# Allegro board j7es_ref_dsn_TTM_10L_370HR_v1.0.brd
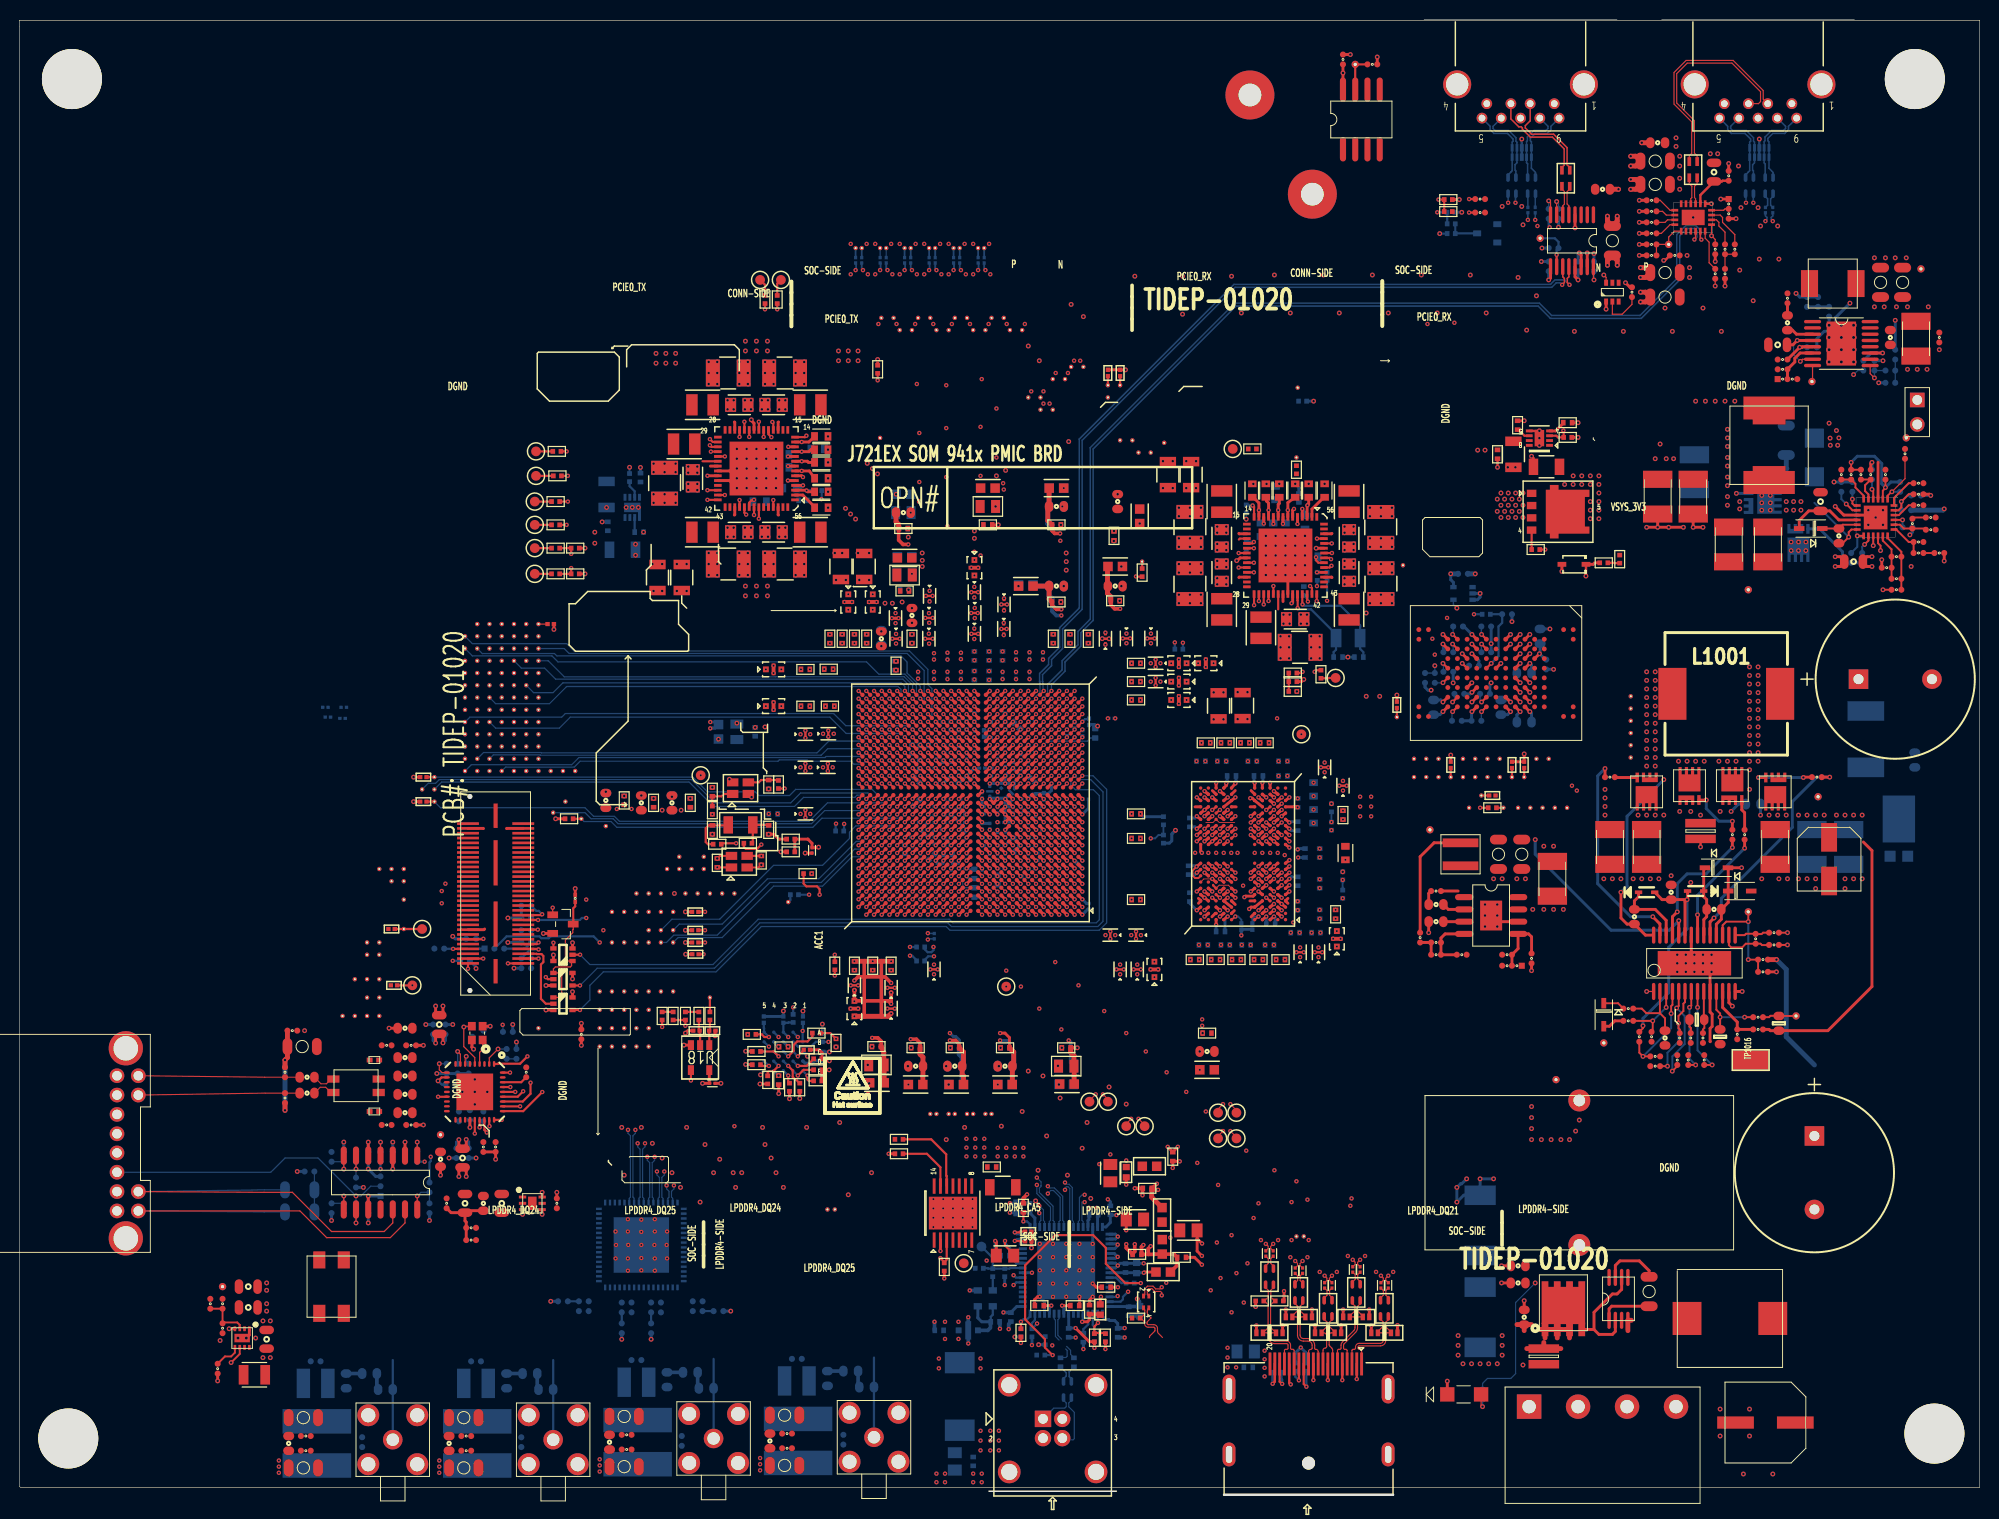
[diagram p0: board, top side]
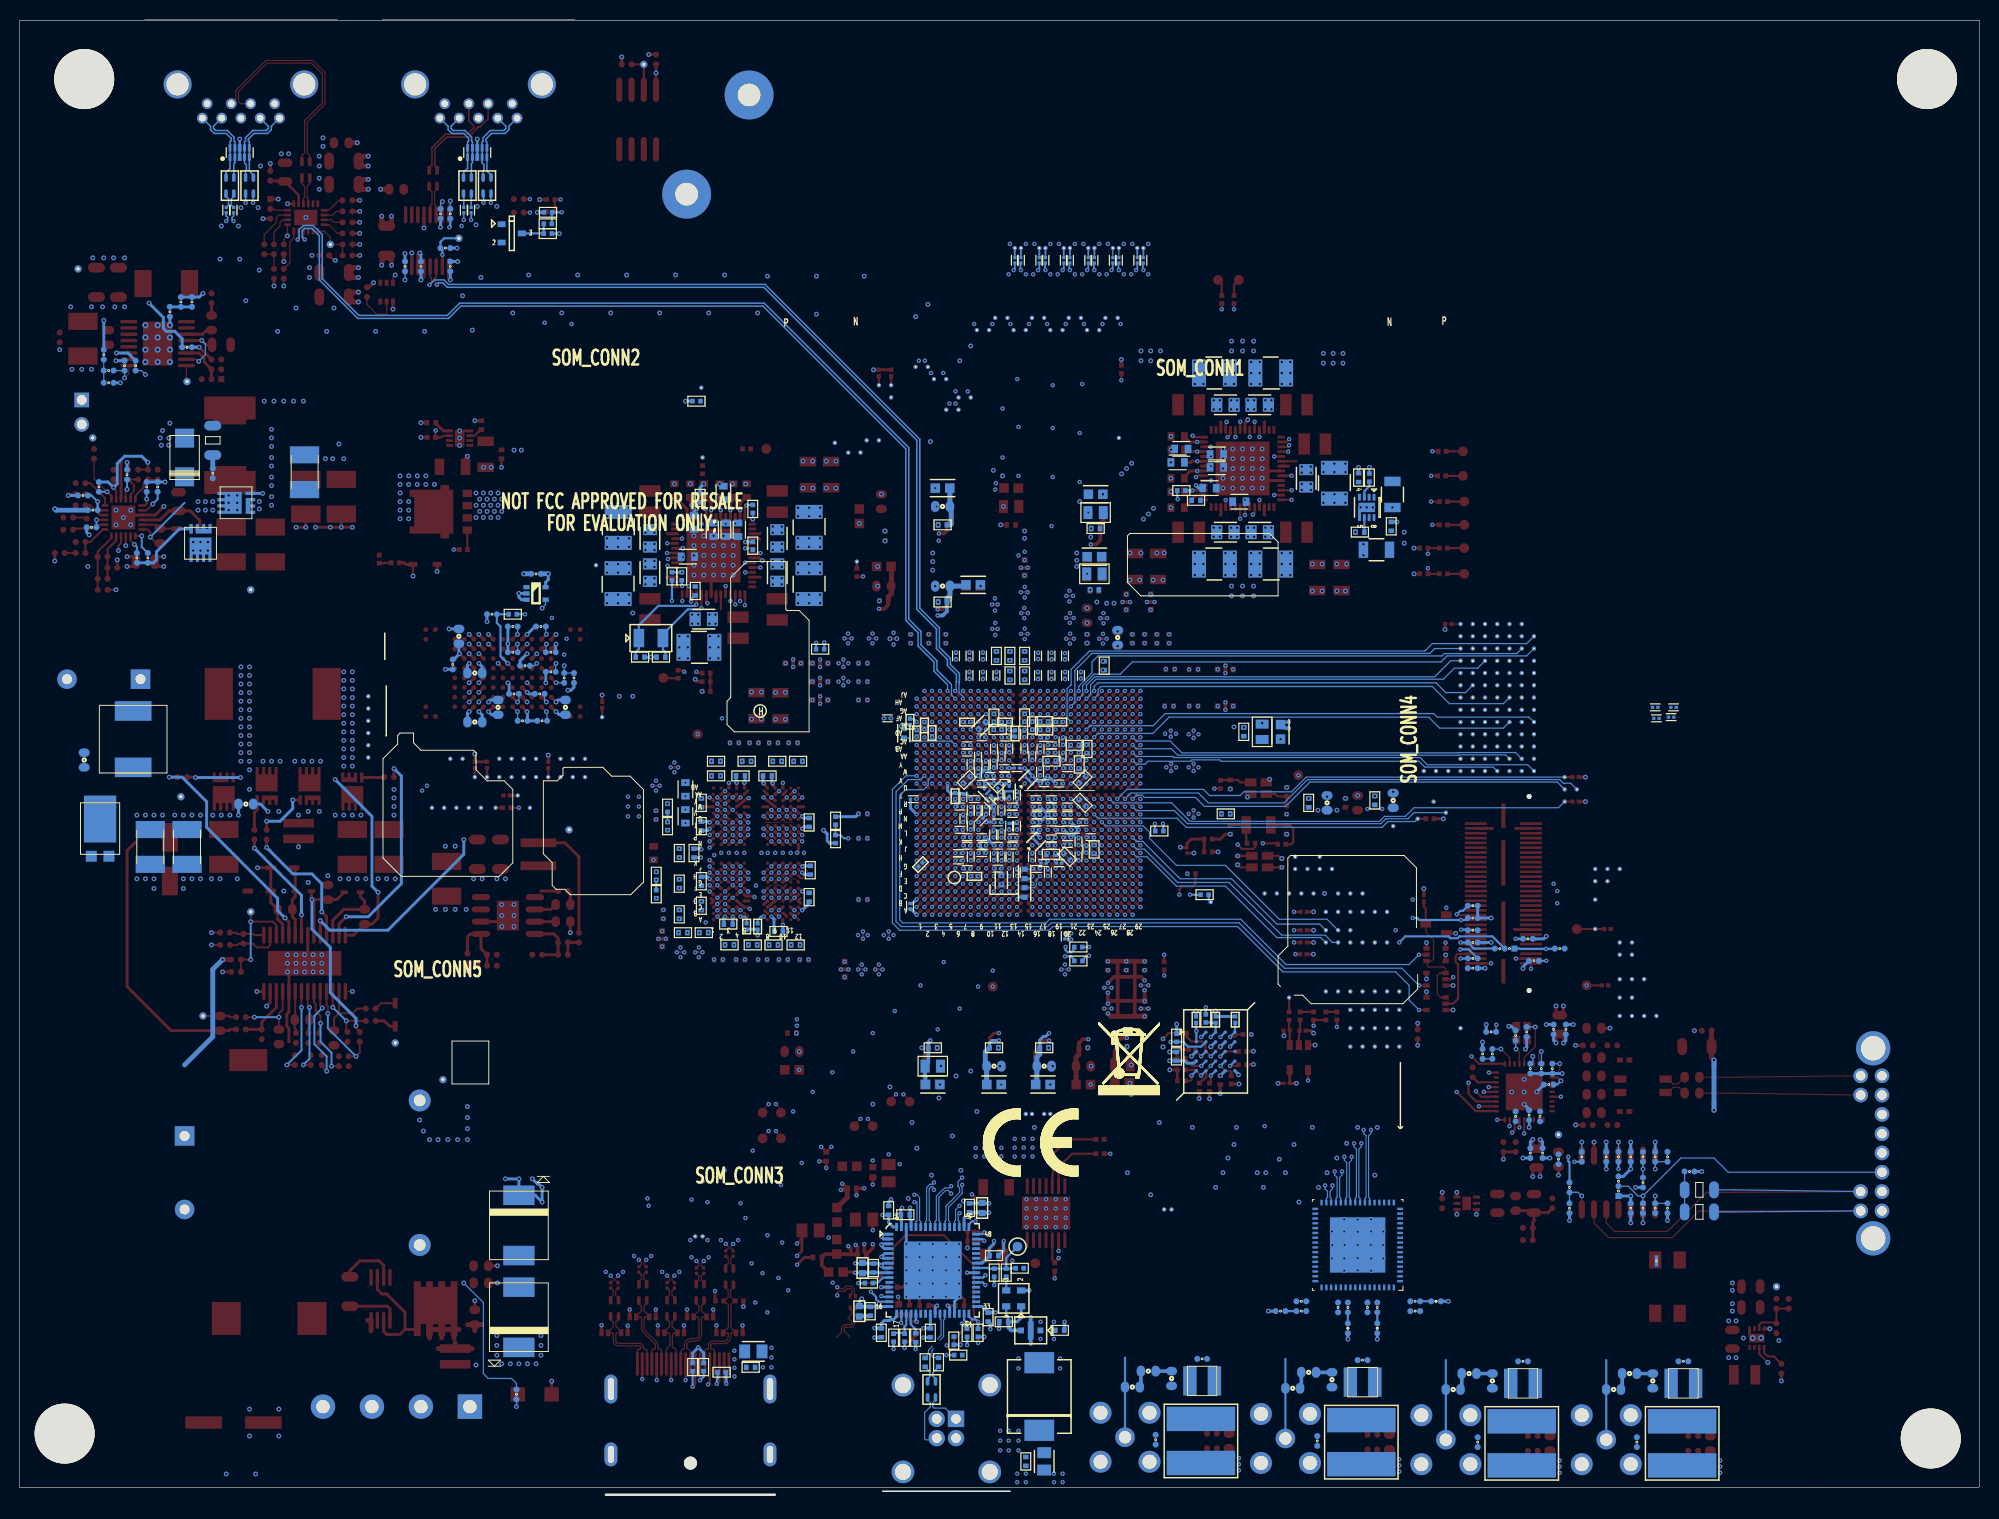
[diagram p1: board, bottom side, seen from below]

Outline 203.33 x 153 mm; copper layers: TOP, L2-SIGNAL, L3-GND, L4-SIGNAL, L5-PWR/GND, L6-PWR/GND, L7-SIGNAL, L8-GND, L9-SIGNAL, BOTTOM. Coordinates in mm from the lower left corner of the outline.
Outline path: 0,152.9 0,0.88 0.13,0.75 203.33,0.75 203.33,152.9 0,152.9

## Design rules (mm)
net group C_PCIE0_TX0: nets C_PCIE0_TX0_N C_PCIE0_TX0_P
net group C_PCIE1_TX0: nets C_PCIE1_TX0_N C_PCIE1_TX0_P
net group C_PCIE1_TX1: nets C_PCIE1_TX1_N C_PCIE1_TX1_P
net group C_PCIE2_TX0: nets C_PCIE2_TX0_N C_PCIE2_TX0_P
net group C_SGMII2_TX0: nets C_SGMII2_TX0_N C_SGMII2_TX0_P
net group C_UB981_DOUT0: nets C_UB981_DOUT0_N C_UB981_DOUT0_P
net group C_USB_SS_TX1: nets C_USB_SS_TX1_N C_USB_SS_TX1_P
net group C_USB_SS_TX2: nets C_USB_SS_TX2_N C_USB_SS_TX2_P
net group CAM_0: nets CAM_0_N CAM_0_P
net group CAM_1: nets CAM_1_N CAM_1_P
net group CAM_2: nets CAM_2_N CAM_2_P
net group CAM_3: nets CAM_3_N CAM_3_P
net group CLKGEN_USB_REFCLK: nets CLKGEN_USB_REFCLK_N CLKGEN_USB_REFCLK_P
net group CON_DP0_AUX: nets CON_DP0_AUX_N CON_DP0_AUX_P
net group CON_DP0_TX0: nets CON_DP0_TX0_N CON_DP0_TX0_P
net group CON_DP0_TX1: nets CON_DP0_TX1_N CON_DP0_TX1_P
net group CONN_USB1_D: nets CONN_USB1_DM CONN_USB1_DP
net group CSI0_RX0: nets CSI0_RX0_N CSI0_RX0_P
net group CSI0_RX1: nets CSI0_RX1_N CSI0_RX1_P
net group CSI0_RX2: nets CSI0_RX2_N CSI0_RX2_P
net group CSI0_RX3: nets CSI0_RX3_N CSI0_RX3_P
net group DP0_AUX: nets DP0_AUX_N DP0_AUX_P
net group MMC0: nets MMC0_CLK MMC0_DS
net group PCIE0_RX0: nets PCIE0_RX0_N PCIE0_RX0_P
net group PCIE0_TX0: nets PCIE0_TX0_N PCIE0_TX0_P
net group PCIE1_RX0: nets PCIE1_RX0_N PCIE1_RX0_P
net group PCIE1_RX1: nets PCIE1_RX1_N PCIE1_RX1_P
net group PCIE1_TX0: nets PCIE1_TX0_N PCIE1_TX0_P
net group PCIE1_TX1: nets PCIE1_TX1_N PCIE1_TX1_P
net group PCIE2_RX0: nets PCIE2_RX0_N PCIE2_RX0_P
net group PCIE2_RX1: nets PCIE2_RX1_N PCIE2_RX1_P
net group PCIE2_TX0: nets PCIE2_TX0_N PCIE2_TX0_P
net group PCIE2_TX1: nets PCIE2_TX1_N PCIE2_TX1_P
net group SGMII2_TX0: nets SGMII2_TX0_N SGMII2_TX0_P
net group SOC_SERDES0_REFCLK: nets SOC_SERDES0_REFCLK_N SOC_SERDES0_REFCLK_P
net group SOC_SERDES1_REFCLK: nets SOC_SERDES1_REFCLK_N SOC_SERDES1_REFCLK_P
net group SOC_SERDES2_REFCLK: nets SOC_SERDES2_REFCLK_N SOC_SERDES2_REFCLK_P
net group TRD: nets TRD_N TRD_P
net group TRD1: nets TRD1_N TRD1_P
net group UFS0_RX0: nets UFS0_RX0_N UFS0_RX0_P
net group UFS0_RX1: nets UFS0_RX1_N UFS0_RX1_P
net group UFS0_TX0: nets UFS0_TX0_N UFS0_TX0_P
net group UFS0_TX1: nets UFS0_TX1_N UFS0_TX1_P
net group USB1_D: nets USB1_DM USB1_DP
net group USB2_D: nets USB2_DM USB2_DP
net group USBC_SS_RX1: nets USBC_SS_RX1_N USBC_SS_RX1_P
net group USBC_SS_RX2: nets USBC_SS_RX2_N USBC_SS_RX2_P
net group USBC_SS_TX1: nets USBC_SS_TX1_N USBC_SS_TX1_P
net group USBC_SS_TX2: nets USBC_SS_TX2_N USBC_SS_TX2_P
net group 40-OHM_PH: nets LPDDR4_CA0 LPDDR4_CA1 LPDDR4_CA2 LPDDR4_CA3 LPDDR4_CA4 LPDDR4_CA5 LPDDR4_CKE0 LPDDR4_CKE1 LPDDR4_CSN0_0 LPDDR4_CSN0_1 LPDDR4_CSN1_0 LPDDR4_CSN1_1
net group MCU_OSPI0: nets MCU_OSPI0_CLK MCU_OSPI0_DQS OSPI_DQS_R
net group MCU_OSPI1: nets MCU_OSPI1_CLK MCU_OSPI1_CLK_R N24594267
net group MCU_RGMII1_T: nets MCU_RGMII1_TD0 MCU_RGMII1_TD1 MCU_RGMII1_TD2 MCU_RGMII1_TD3 MCU_RGMII1_TX_CTL MCU_RGMII1_TXC
net group MMC1: nets MMC1_CLK MMC1_CMD MMC1_DAT0 MMC1_DAT1 MMC1_DAT2 MMC1_DAT3
net group PRG0_RGMII1: nets MCASP0_AXR7/PRG0_RGMII1_TD0 MCASP0_AXR8/PRG0_RGMII1_TD1 MCASP0_AXR9/PRG0_RGMII1_TD2 MCASP0_AXR10/PRG0_RGMII1_TD3 MCASP0_AXR11/PRG0_RGMII1_TX_CTL MCASP0_AXR12/PRG0_RGMII1_TXC
net group PRG0_RGMII2_T: nets GPIO0_78/PRG0_RGMII2_TX_CTL GPIO0_79/PRG0_RGMII2_TXC MCASP1_AXR7/PRG0_RGMII2_TD0 MCASP1_AXR8/PRG0_RGMII2_TD1 PRG0_RGMII2_TD2 PRG0_RGMII2_TD3
net group PWR_PH: nets VCC_LM5141 VCC_LM5175 VDDA_LM5141 VDDI_MMC2 VOSNS
net group SOC_MCU_OSPI0: nets SOC_MCU_OSPI0_CLK_R
net group VOUT0_GROUP: nets VOUT0_DATA11/PRG1_RGMII2_TD0 VOUT0_DATA12/PRG1_RGMII2_TD1 VOUT0_DATA13/PRG1_RGMII2_TD2 VOUT0_DATA14/PRG1_RGMII2_TD3 VOUT0_DATA15/PRG1_RGMII2_TX_CTL VOUT0_DATA16/PRG1_RGMII1_TD0 VOUT0_DATA17/PRG1_RGMII1_TD1 VOUT0_DATA18/PRG1_RGMII1_TD2 VOUT0_DATA19/PRG1_RGMII1_TD3 VOUT0_DATA20/PRG1_RGMII1_TX_CTL VOUT0_DATA21/PRG1_RGMII1_TXC VOUT0_HSYNC/PRG1_RGMII2_TXC VOUT0_PCLK/SPI6_D1

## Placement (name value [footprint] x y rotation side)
C26  47uF  [CAP1206_2]  66.19 95.11 90 top
C27  47uF  [CAP1206_2]  68.71 95.11 90 top
C28  47uF  [CAP1206_2]  85.22 96.26 90 top
C29  47uF  [CAP1206_2]  87.63 96.26 90 top
C30  1uF  [CAP0402_0-75]  100.46 100.57 0 top
C31  22uF  [CAP0805_1-25]  100.46 102.48 0 top
C32  1uF  [EMIFIL_NFM15CC_0402_0-5]  94.41 93.21 270 top
C33  10uF  [EMIFIL_NFM18C_0603_0-7]  99.06 96.13 270 top
C34  1uF  [CAP0402_0-75]  91.69 100.19 0 top
C35  4.7uF  [C603-35X45]  91.69 101.84 0 top
C37  1uF  [EMIFIL_NFM15CC_0402_0-5]  99.1 91.43 270 top
C38  1uF  [EMIFIL_NFM15CC_0402_0-5]  99.06 93.59 270 top
C41  10uF  [EMIFIL_NFM18C_0603_0-7]  85.98 92.57 270 top
C42  10uF  [EMIFIL_NFM18C_0603_0-7]  88.52 92.57 270 top
C43  1uF  [CAP0402_0-75]  91.82 93.84 0 bottom
C44  22uF  [CAP0805_1-25]  91.82 95.49 0 bottom
C45  1uF  [CAP0402_0-75]  107.57 100.57 0 top
C46  4.7uF  [C603-35X45]  107.57 102.48 0 top
C47  1uF  [CAP0402_0-75]  107.57 92.57 0 top
C48  4.7uF  [C603-35X45]  107.57 94.22 0 top
C49  1uF  [CAP0402_0-75]  113.66 92.7 0 top
C50  4.7uF  [C603-35X45]  113.66 94.22 0 top
C53  1uF  [EMIFIL_NFM15CC_0402_0-5]  90.88 90.9 270 top
C54  1uF  [EMIFIL_NFM15CC_0402_0-5]  83.91 78.91 0 top
C55  47uF  [CAP1206_2]  119.13 105.78 90 top
C56  47uF  [CAP1206_2]  121.54 105.78 90 top
C57  1uF  [EMIFIL_NFM15CC_0402_0-5]  114.83 88.79 270 top
C58  1uF  [EMIFIL_NFM15CC_0402_0-5]  117.37 88.79 270 top
C59  10uF  [EMIFIL_NFM18C_0603_0-7]  78.23 81.78 0 top
C60  0.47uF  [CAP0402_0-75]  84.07 88.76 90 top
C61  0.47uF  [CAP0402_0-75]  85.34 88.76 90 top
C62  0.47uF  [CAP0402_0-75]  86.61 88.76 90 top
C63  0.47uF  [CAP0402_0-75]  87.88 88.76 90 top
C64  1uF  [EMIFIL_NFM15CC_0402_0-5]  99.06 89.27 270 top
C65  1uF  [EMIFIL_NFM15CC_0402_0-5]  94.35 90.92 270 top
C66  1uF  [EMIFIL_NFM15CC_0402_0-5]  94.34 88.76 270 top
C67  1uF  [EMIFIL_NFM15CC_0402_0-5]  90.93 88.76 270 top
C68  1uF  [EMIFIL_NFM15CC_0402_0-5]  102.87 72.84 45 bottom
C69  1uF  [EMIFIL_NFM15CC_0402_0-5]  100.66 72.94 270 bottom
C70  1uF  [EMIFIL_NFM15CC_0402_0-5]  112.65 88.76 90 top
C71  0.47uF  [CAP0402_0-75]  108.97 88.76 90 top
C72  0.47uF  [CAP0402_0-75]  110.87 88.76 90 top
C73  0.47uF  [CAP0402_0-75]  107.24 88.76 90 top
C78  10uF  [EMIFIL_NFM18C_0603_0-7]  120.27 86.22 180 top
C79  0.47uF  [CAP0402_0-75]  115.82 86.22 0 top
C80  10uF  [EMIFIL_NFM18C_0603_0-7]  78.23 85.59 0 top
C81  0.47uF  [CAP0402_0-75]  81.53 85.59 180 top
C82  0.47uF  [CAP0402_0-75]  115.82 84.32 0 top
C83  47uF  [CAP1206_2]  126.87 81.83 270 top
C84  10uF  [EMIFIL_NFM18C_0603_0-7]  120.27 84.32 180 top
C85  0.47uF  [CAP0402_0-75]  84.07 81.78 180 top
C86  0.1uF  [CAP0402_0-75]  160.59 111.17 0 top
C87  0.47uF  [CAP0402_0-75]  115.82 82.41 0 top
C88  22uF  [CAP1206_2]  158.39 106.59 180 top
C89  220pF  [CAP0402_0-75]  155.4 110.91 90 top
C90  0.47uF  [CAP0402_0-75]  81.53 81.78 180 top
C91  10uF  [EMIFIL_NFM18C_0603_0-7]  120.27 82.41 180 top
C92  47uF  [CAP1206_2]  124.38 81.8 270 top
C93  1uF  [EMIFIL_NFM15CC_0402_0-5]  117.86 84.32 180 top
C94  0.47uF  [CAP0402_0-75]  83.95 85.61 180 top
C95  10uF  [EMIFIL_NFM18C_0603_0-7]  123.06 86.22 180 top
C96  0.1uF  [CAP0402_0-75]  153.31 107.89 270 top
C97  22uF  [CAP1206_2]  154.97 107.89 270 top
C98  1uF  [EMIFIL_NFM15CC_0402_0-5]  97.87 67.73 135 bottom
C99  1uF  [EMIFIL_NFM15CC_0402_0-5]  81.53 78.86 0 top
C100  1uF  [EMIFIL_NFM15CC_0402_0-5]  117.86 86.22 180 top
C101  0.01uF  [CAP0402_0-75]  123.06 77.97 0 top
C102  0.1uF  [CAP0402_0-75]  129.16 77.97 0 top
C104  4.7uF  [C603-35X45]  60.83 72 90 top
C105  4.7uF  [C603-35X45]  92.58 91.18 90 top
C106  1uF  [EMIFIL_NFM15CC_0402_0-5]  98.68 74.16 135 bottom
C107  1uF  [EMIFIL_NFM15CC_0402_0-5]  81.53 75.43 0 top
C110  30pF  [CAP0402_0-75]  77.72 73.65 270 top
C111  1uF  [CAP0402_0-75]  62.74 72 90 top
C112  1uF  [CAP0402_0-75]  92.58 88.76 90 top
C114  30pF  [CAP0402_0-75]  71.88 72.89 90 top
C118  1uF  [EMIFIL_NFM15CC_0402_0-5]  83.86 75.43 0 top
C119  1uF  [EMIFIL_NFM15CC_0402_0-5]  81.53 70.6 0 top
C120  0.47uF  [CAP0402_0-75]  115.82 70.6 0 top
C121  22uF  [CAP0805_1-25]  88.9 44.57 180 top
C122  4.7uF  [C603-35X45]  67.69 71.74 90 top
C124  18pF  [CAP0402_0-75]  71.88 68.95 270 top
C125  18pF  [CAP0402_0-75]  77.72 68.95 270 top
C128  0.47uF  [CAP0402_0-75]  115.82 68.06 0 top
C130  1uF  [CAP0402_0-75]  88.9 46.47 180 top
C131  1uF  [CAP0402_0-75]  69.6 71.74 90 top
C132  0.1uF  [CAP0201_0-5]  82.22 66.82 270 top
C133  10uF  [CAP0603_1]  137.54 66.54 270 top
C135  12pF  [CAP0402_0-75]  76.96 65.78 270 top
C136  12pF  [CAP0402_0-75]  72.39 65.52 90 top
C141  0.47uF  [CAP0402_0-75]  115.82 61.71 0 top
C149  1uF  [EMIFIL_NFM15CC_0402_0-5]  115.82 58.03 180 top
C155  1uF  [CAP0402_0-75]  126.24 55.49 0 top
C156  0.01uF  [CAP0402_0-75]  130.81 55.49 0 top
C157  0.47uF  [CAP0402_0-75]  86.61 54.85 270 top
C158  0.47uF  [CAP0402_0-75]  88.52 54.85 270 top
C159  0.47uF  [CAP0402_0-75]  90.42 54.85 270 top
C160  1uF  [EMIFIL_NFM15CC_0402_0-5]  90.42 52.57 90 top
C161  1uF  [EMIFIL_NFM15CC_0402_0-5]  94.87 54.47 90 top
C162  0.47uF  [CAP0402_0-75]  125.09 77.97 0 top
C163  0.47uF  [CAP0402_0-75]  127.13 77.97 0 top
C164  0.47uF  [CAP0402_0-75]  124.08 55.49 0 top
C165  0.47uF  [CAP0402_0-75]  136.52 60.19 270 top
C166  1uF  [EMIFIL_NFM15CC_0402_0-5]  135.38 75.43 90 top
C167  1uF  [EMIFIL_NFM15CC_0402_0-5]  113.16 58.03 180 top
C168  1uF  [EMIFIL_NFM15CC_0402_0-5]  114.17 54.47 90 top
C169  0.47uF  [CAP0402_0-75]  137.29 70.47 270 top
C173  0.1uF  [CAP0201_0-5]  71.88 42.66 0 top
C177  0.47uF  [CAP0402_0-75]  128.52 55.49 0 top
C178  0.47uF  [CAP0402_0-75]  121.92 55.49 0 top
C179  1uF  [EMIFIL_NFM15CC_0402_0-5]  137.29 73.52 90 top
C180  1uF  [EMIFIL_NFM15CC_0402_0-5]  134.75 56.25 90 top
C181  1uF  [EMIFIL_NFM15CC_0402_0-5]  115.95 54.47 90 top
C182  10uF  [EMIFIL_NFM18C_0603_0-7]  117.73 54.47 90 top
C184  10uF  [EMIFIL_NFM18C_0603_0-7]  86.61 50.41 90 top
C185  4.7uF  [C603-35X45]  92.96 44.44 180 top
C186  1uF  [CAP0402_0-75]  92.96 46.34 180 top
C187  4.7uF  [C603-35X45]  97.03 44.44 180 top
C188  1uF  [CAP0402_0-75]  97.03 46.34 180 top
C189  22uF  [CAP0805_1-25]  108.58 44.44 180 top
C190  1uF  [CAP0402_0-75]  108.58 46.34 180 top
C192  10uF  [EMIFIL_NFM18C_0603_0-7]  136.65 57.65 90 top
C193  1uF  [EMIFIL_NFM15CC_0402_0-5]  132.84 56.25 90 top
C197  1uF  [EMIFIL_NFM15CC_0402_0-5]  90.42 50.41 90 top
C198  1uF  [EMIFIL_NFM15CC_0402_0-5]  86.61 52.82 90 top
C199  4.7uF  [C603-35X45]  102.23 44.44 180 top
C200  1uF  [CAP0402_0-75]  102.23 46.34 180 top
C201  4.7uF  [C603-35X45]  123.19 45.96 180 top
C202  1uF  [CAP0402_0-75]  123.19 47.87 180 top
C203  0.1uF  [CAP0402_0-75]  64.42 105.47 90 bottom
C204  220pF  [CAP0402_0-75]  64.29 99.82 0 bottom
C205  4.7uF  [CAP0402_0-75]  79.27 46.45 0 top
C206  0.1uF  [CAP0402_0-75]  78.77 42.99 270 top
C208  0.1uF  [CAP0402_0-75]  61.04 100.42 90 bottom
C210  22uF  [CAP1206_2]  60.91 103.72 270 bottom
C211  22uF  [CAP1206_2]  62.56 97.99 0 bottom
C212  0.22uF  [CAP0201_0-5]  97.54 128.01 90 bottom
C213  0.22uF  [CAP0201_0-5]  96.9 128.01 90 bottom
C214  0.1uF  [CAP0201_0-5]  89.92 128.01 90 bottom
C215  0.1uF  [CAP0201_0-5]  89.28 128.01 90 bottom
C216  0.22uF  [CAP0201_0-5]  181.86 133.21 90 bottom
C217  0.22uF  [CAP0201_0-5]  181.1 133.21 90 bottom
C218  0.22uF  [CAP0201_0-5]  157.23 133.21 90 bottom
C219  0.22uF  [CAP0201_0-5]  156.46 133.21 90 bottom
C220  0.22uF  [CAP0201_0-5]  100.08 128.01 90 bottom
C221  0.22uF  [CAP0201_0-5]  99.44 128.01 90 bottom
C222  0.22uF  [CAP0201_0-5]  92.46 128.01 90 bottom
C223  0.22uF  [CAP0201_0-5]  91.82 128.01 90 bottom
C224  0.22uF  [CAP0201_0-5]  95 128.01 90 bottom
C225  0.22uF  [CAP0201_0-5]  94.36 128.01 90 bottom
C226  0.22uF  [CAP0201_0-5]  87.38 128.01 90 bottom
C227  0.22uF  [CAP0201_0-5]  86.74 128.01 90 bottom
C228  0.1uF  [C402-25RD]  79.63 4.82 0 top
C234  0.1uF  [C402-25RD]  79.63 6.34 0 top
C236  22uF  [CAP0805_1-25]  91.69 101.84 0 bottom
C237  1uF  [CAP0402_0-75]  91.69 100.19 0 bottom
C238  4.7uF  [C603-35X45]  89.41 88.89 90 bottom
C239  1uF  [CAP0402_0-75]  90.81 85.97 90 bottom
C242  4.7uF  [C603-35X45]  107.57 94.22 0 bottom
C243  1uF  [CAP0402_0-75]  107.57 92.57 0 bottom
C244  4.7uF  [C603-35X45]  107.57 102.48 0 bottom
C245  1uF  [CAP0402_0-75]  107.57 100.57 0 bottom
C246  22uF  [CAP0805_1-25]  91.82 95.37 0 top
C247  1uF  [CAP0402_0-75]  91.82 93.72 0 top
C249  10uF  [C1206-40X70]  79.38 8.24 0 top
C252  0.1uF  [CAP0201_0-5]  106.17 86.98 90 bottom
C253  0.1uF  [CAP0201_0-5]  104.78 86.98 90 bottom
C254  0.47uF  [CAP0402_0-75]  100.58 86.98 90 bottom
C255  0.47uF  [CAP0402_0-75]  99.06 86.98 90 bottom
C256  0.1uF  [CAP0201_0-5]  97.66 86.98 90 bottom
C257  0.1uF  [CAP0201_0-5]  96.27 86.98 90 bottom
C258  0.1uF  [CAP0201_0-5]  103.38 86.98 90 bottom
C259  0.1uF  [CAP0201_0-5]  94.87 86.98 90 bottom
C260  1uF  [EMIFIL_NFM15CC_0402_0-5]  102.13 92.32 270 top
C261  0.1uF  [CAP0201_0-5]  113.28 80.51 0 bottom
C262  0.1uF  [CAP0201_0-5]  104.78 84.95 90 bottom
C263  0.1uF  [CAP0201_0-5]  103.38 84.95 90 bottom
C264  0.1uF  [CAP0201_0-5]  101.98 84.95 90 bottom
C265  0.47uF  [CAP0402_0-75]  101.98 86.98 90 bottom
C266  0.47uF  [CAP0402_0-75]  100.58 84.95 90 bottom
C267  0.47uF  [CAP0402_0-75]  99.06 84.95 90 bottom
C268  0.1uF  [CAP0201_0-5]  97.66 84.95 90 bottom
C269  0.1uF  [CAP0201_0-5]  96.27 84.95 90 bottom
C270  0.1uF  [CAP0201_0-5]  94.87 84.95 90 bottom
C271  0.1uF  [CAP0201_0-5]  93.22 84.95 90 bottom
C272  1uF  [EMIFIL_NFM15CC_0402_0-5]  102.11 89.78 270 top
C273  22uF  [CAP0805_1-25]  74.42 79.11 90 bottom
C274  0.1uF  [CAP0201_0-5]  97.03 78.48 0 bottom
C275  0.1uF  [CAP0201_0-5]  95.12 78.09 270 bottom
C276  0.1uF  [CAP0201_0-5]  105.03 77.71 180 bottom
C277  0.1uF  [CAP0201_0-5]  96.27 77.71 0 bottom
C278  1uF  [CAP0402_0-75]  93.85 77.71 0 bottom
C279  0.1uF  [CAP0201_0-5]  102.23 77.33 270 bottom
C280  0.1uF  [CAP0201_0-5]  97.41 77.33 270 bottom
C281  1uF  [CAP0402_0-75]  92.58 77.33 90 bottom
C282  0.1uF  [CAP0201_0-5]  105.03 76.95 0 bottom
C283  0.1uF  [CAP0201_0-5]  96.27 76.95 180 bottom
C284  1uF  [CAP0402_0-75]  76.33 79.11 90 bottom
C285  0.1uF  [CAP0201_0-5]  95.12 76.57 270 bottom
C286  0.1uF  [CAP0201_0-5]  104.67 75.73 90 bottom
C287  0.1uF  [CAP0402_0-75]  131.06 76.06 180 bottom
C288  0.01uF  [CAP0402_0-75]  127.89 76.06 180 bottom
C289  0.01uF  [CAP0402_0-75]  124.71 76.06 180 bottom
C290  0.01uF  [CAP0402_0-75]  122.55 76.06 180 bottom
C291  1uF  [CAP0402_0-75]  96.27 76.06 0 bottom
C292  0.1uF  [CAP0201_0-5]  99.86 75.35 0 bottom
C293  1uF  [CAP0402_0-75]  93.4 75.73 90 bottom
C294  0.1uF  [CAP0201_0-5]  103.12 75.68 90 bottom
C295  4.7uF  [C603-35X45]  89.41 88.76 90 top
C296  4.7uF  [C603-35X45]  60.83 72 90 bottom
C297  0.1uF  [CAP0201_0-5]  97.45 74.94 90 bottom
C298  0.1uF  [CAP0201_0-5]  103.89 74.92 90 bottom
C299  0.1uF  [CAP0201_0-5]  94.61 75.34 180 bottom
C300  0.1uF  [CAP0201_0-5]  103.92 70.94 90 bottom
C301  0.01uF  [CAP0402_0-75]  131.06 74.54 180 bottom
C302  0.01uF  [CAP0402_0-75]  128.52 74.54 180 bottom
C303  0.01uF  [CAP0402_0-75]  125.73 74.54 0 bottom
C304  0.1uF  [CAP0201_0-5]  102.62 74.54 0 bottom
C305  0.1uF  [CAP0201_0-5]  33.66 81.65 0 bottom
C306  1uF  [CAP0402_0-75]  93.06 74.15 315 bottom
C307  1uF  [CAP0402_0-75]  105.05 74.13 135 bottom
C308  0.1uF  [CAP0201_0-5]  103.45 73.73 0 bottom
C309  0.1uF  [CAP0201_0-5]  33.53 80.51 180 bottom
C310  0.1uF  [CAP0201_0-5]  97.03 73.78 180 bottom
C311  0.1uF  [CAP0201_0-5]  95.48 73.75 180 bottom
C312  10uF  [CAP0603_1]  134.24 73.14 270 bottom
C313  1uF  [CAP0402_0-75]  90.93 85.97 90 top
C314  1uF  [CAP0402_0-75]  62.74 72 90 bottom
C315  0.1uF  [CAP0402_0-75]  78.19 70.6 180 bottom
C316  0.1uF  [CAP0201_0-5]  105.41 72.38 90 bottom
C317  0.1uF  [CAP0201_0-5]  110.62 72.13 0 bottom
C318  0.1uF  [CAP0201_0-5]  104.27 72.13 0 bottom
C319  0.1uF  [CAP0201_0-5]  101.65 73.47 315 bottom
C320  0.1uF  [CAP0201_0-5]  99.86 72.53 90 bottom
C321  0.1uF  [CAP0201_0-5]  97.92 72.13 180 bottom
C322  0.1uF  [CAP0201_0-5]  96.27 72.13 180 bottom
C323  0.01uF  [CAP0402_0-75]  132.59 71.74 90 bottom
C324  0.1uF  [CAP0201_0-5]  103.06 70.97 270 bottom
C325  1uF  [CAP0402_0-75]  93.05 71.75 45 bottom
C326  0.1uF  [CAP0201_0-5]  105.79 71.36 180 bottom
C327  0.1uF  [CAP0201_0-5]  102.62 71.69 45 bottom
C328  0.1uF  [CAP0201_0-5]  100.33 71.36 0 bottom
C329  0.1uF  [CAP0201_0-5]  97.79 71.36 0 bottom
C330  0.1uF  [CAP0201_0-5]  96.27 71.36 0 bottom
C331  0.1uF  [CAP0201_0-5]  94.61 71.36 0 bottom
C332  0.1uF  [CAP0201_0-5]  104.65 70.98 270 bottom
C333  0.1uF  [CAP0201_0-5]  100.33 70.6 180 bottom
C334  0.1uF  [CAP0201_0-5]  101.85 69.71 180 bottom
C335  0.1uF  [CAP0201_0-5]  97.79 70.47 180 bottom
C336  0.1uF  [CAP0201_0-5]  96.27 70.47 180 bottom
C337  0.1uF  [CAP0201_0-5]  94.61 70.47 180 bottom
C338  10uF  [CAP0603_1]  134.24 70.35 270 bottom
C339  0.1uF  [CAP0201_0-5]  105.41 70.09 270 bottom
C340  0.1uF  [CAP0201_0-5]  100.66 69.33 270 bottom
C341  0.01uF  [CAP0402_0-75]  121.41 69.71 270 bottom
C342  0.1uF  [CAP0201_0-5]  97.79 69.71 0 bottom
C343  0.1uF  [CAP0201_0-5]  96.27 69.71 0 bottom
C344  0.1uF  [CAP0201_0-5]  94.61 69.71 0 bottom
C345  0.01uF  [CAP0402_0-75]  132.59 69.33 270 bottom
C346  0.1uF  [CAP0201_0-5]  104.65 69.33 270 bottom
C348  4.7uF  [C603-35X45]  67.69 71.74 90 bottom
C349  4.7uF  [C603-35X45]  64.52 71.74 90 top
C350  0.1uF  [CAP0201_0-5]  105.79 68.95 0 bottom
C351  0.1uF  [CAP0201_0-5]  101.47 72.51 90 bottom
C352  0.1uF  [CAP0201_0-5]  99.85 69.33 270 bottom
C353  0.1uF  [CAP0201_0-5]  97.92 68.95 180 bottom
C354  0.1uF  [CAP0201_0-5]  95.38 68.95 0 bottom
C355  0.1uF  [CAP0201_0-5]  93.85 68.95 0 bottom
C356  0.1uF  [CAP0201_0-5]  105.03 68.19 0 bottom
C357  0.1uF  [CAP0201_0-5]  103.5 68.19 0 bottom
C358  0.1uF  [CAP0201_0-5]  94.61 68.19 0 bottom
C359  0.1uF  [CAP0201_0-5]  92.2 68.19 180 bottom
C360  0.1uF  [CAP0201_0-5]  32 80.63 0 bottom
C361  0.1uF  [CAP0201_0-5]  96.27 68.06 0 bottom
C362  0.1uF  [CAP0201_0-5]  93.47 67.73 90 bottom
C363  0.1uF  [CAP0201_0-5]  105.03 67.3 180 bottom
C364  0.1uF  [CAP0201_0-5]  103.38 67.3 180 bottom
C365  0.1uF  [CAP0201_0-5]  101.85 67.3 180 bottom
C366  0.1uF  [CAP0201_0-5]  100.33 67.3 180 bottom
C367  0.1uF  [CAP0201_0-5]  31.75 81.65 180 bottom
C368  0.1uF  [CAP0201_0-5]  96.27 67.3 180 bottom
C369  1uF  [CAP0402_0-75]  69.6 71.74 90 bottom
C370  1uF  [CAP0402_0-75]  65.79 71.74 90 top
C371  0.1uF  [CAP0201_0-5]  95.49 65.49 0 bottom
C372  1uF  [CAP0402_0-75]  91.85 66.92 270 bottom
C373  0.01uF  [CAP0402_0-75]  134.87 66.54 270 bottom
C374  0.01uF  [CAP0402_0-75]  133.35 66.54 270 bottom
C375  0.1uF  [CAP0201_0-5]  105.92 66.54 180 bottom
C376  0.1uF  [CAP0201_0-5]  103.5 66.54 0 bottom
C377  1uF  [CAP0402_0-75]  96.33 66.41 0 bottom
C378  0.1uF  [CAP0201_0-5]  104.65 66.16 270 bottom
C379  1uF  [CAP0402_0-75]  94.65 66.15 225 bottom
C380  0.1uF  [CAP0201_0-5]  93.47 66.16 90 bottom
C381  0.1uF  [CAP0201_0-5]  105.92 65.78 0 bottom
C382  0.1uF  [CAP0201_0-5]  92.66 66.92 90 bottom
C383  0.1uF  [CAP0201_0-5]  105.03 64.89 0 bottom
C384  0.01uF  [CAP0402_0-75]  121.28 64.76 270 bottom
C385  0.1uF  [CAP0201_0-5]  96.65 64.51 90 bottom
C386  0.01uF  [CAP0402_0-75]  132.59 63.62 90 bottom
C387  0.01uF  [CAP0402_0-75]  134.87 63.36 270 bottom
C388  0.01uF  [CAP0402_0-75]  121.41 61.97 270 bottom
C389  0.01uF  [CAP0402_0-75]  132.59 61.08 270 bottom
C390  0.1uF  [CAP0201_0-5]  110.95 61.03 90 bottom
C391  0.01uF  [CAP0402_0-75]  134.87 60.19 270 bottom
C392  0.01uF  [CAP0402_0-75]  129.79 59.17 0 bottom
C393  0.01uF  [CAP0402_0-75]  124.59 58.41 180 bottom
C394  0.1uF  [CAP0402_0-75]  134.49 58.28 0 bottom
C395  0.01uF  [CAP0402_0-75]  132.33 58.28 180 bottom
C396  0.1uF  [CAP0201_0-5]  94.9 57.92 270 bottom
C397  0.01uF  [CAP0402_0-75]  129.67 57.01 180 bottom
C398  0.01uF  [CAP0402_0-75]  127.25 57.01 180 bottom
C399  0.01uF  [CAP0402_0-75]  125.09 57.01 180 bottom
C400  0.01uF  [CAP0402_0-75]  122.81 57.01 180 bottom
C402  1uF  [CAP0402_0-75]  108.58 46.34 180 bottom
C403  22uF  [CAP0805_1-25]  108.58 44.44 180 bottom
C404  1uF  [CAP0402_0-75]  97.03 46.34 180 bottom
C405  4.7uF  [C603-35X45]  97.03 44.44 180 bottom
C410  1uF  [CAP0402_0-75]  102.23 46.34 180 bottom
C411  4.7uF  [C603-35X45]  102.23 44.44 180 bottom
C413  0.1uF  [CAP0402_0-75]  83.31 45.46 90 bottom
C414  0.22uF  [CAP0201_0-5]  130.05 25.01 270 top
C415  0.22uF  [CAP0201_0-5]  129.29 25.01 270 top
C416  0.22uF  [CAP0201_0-5]  132.33 23.23 270 top
C417  0.22uF  [CAP0201_0-5]  133.1 23.23 270 top
C418  0.22uF  [CAP0201_0-5]  135.38 21.71 270 top
C419  0.22uF  [CAP0201_0-5]  136.14 21.71 270 top
C420  0.22uF  [CAP0201_0-5]  138.3 23.36 270 top
C421  0.22uF  [CAP0201_0-5]  139.06 23.36 270 top
C422  0.22uF  [CAP0201_0-5]  141.22 21.71 270 top
C423  0.22uF  [CAP0201_0-5]  141.99 21.71 270 top
C425  0.1uF  [CAP0201_0-5]  93 69.73 0 bottom
C427  0.1uF  [CAP0201_0-5]  103.58 69.95 135 bottom
C428  0.1uF  [CAP0201_0-5]  101.46 70.97 270 bottom
C429  0.1uF  [CAP0201_0-5]  101.46 68.43 90 bottom
C430  0.1uF  [CAP0201_0-5]  103.89 76.49 90 bottom
C431  0.1uF  [CAP0201_0-5]  102.26 75.78 270 bottom
C432  0.1uF  [CAP0201_0-5]  101.45 76.57 270 bottom
C433  0.1uF  [CAP0201_0-5]  98.26 76.57 270 bottom
C434  0.1uF  [CAP0201_0-5]  97.81 64.89 0 bottom
C435  0.1uF  [CAP0201_0-5]  100.65 77.36 270 bottom
C436  0.1uF  [CAP0201_0-5]  99.09 77.37 270 bottom
C437  0.1uF  [CAP0201_0-5]  102.26 66.17 90 bottom
C438  0.1uF  [CAP0201_0-5]  101.46 66.14 270 bottom
C439  0.1uF  [CAP0201_0-5]  101.85 64.92 0 bottom
C440  0.1uF  [CAP0201_0-5]  100.62 66.13 90 bottom
C441  0.1uF  [CAP0201_0-5]  99.87 64.51 270 bottom
C442  0.1uF  [CAP0201_0-5]  98.29 66.15 90 bottom
C443  0.1uF  [CAP0201_0-5]  103.48 78.54 180 bottom
C444  0.1uF  [CAP0201_0-5]  99.12 78.89 90 bottom
C445  0.1uF  [CAP0201_0-5]  101.09 78.52 180 bottom
C446  0.1uF  [CAP0201_0-5]  97.09 65.5 0 bottom
C449  0.1uF  [CAP0201_0-5]  100.25 68.14 0 bottom
C450  0.1uF  [CAP0201_0-5]  101.1 74.53 0 bottom
C451  0.1uF  [CAP0201_0-5]  94.62 67.48 180 bottom
C452  0.1uF  [CAP0201_0-5]  102.32 68.46 90 bottom
C453  0.1uF  [CAP0201_0-5]  101.15 75.34 180 bottom
C481  2.2uF  [CAP0603_1]  133.35 100.83 270 bottom
C482  47uF  [CAP1210_2-75]  141.22 94.48 90 bottom
C483  47uF  [CAP1210_2-75]  141.22 94.48 90 top
C484  10uF  [CAP0805_1-5]  124.71 99.18 270 top
C485  10uF  [CAP0805_1-5]  137.92 99.18 270 bottom
C486  10uF  [CAP0805_1-5]  124.71 99.18 270 bottom
C487  10uF  [CAP0805_1-5]  124.71 95.62 90 top
C488  10uF  [CAP0805_1-5]  137.92 95.62 90 top
C489  10uF  [CAP0805_1-5]  137.92 99.18 270 top
C490  10uF  [CAP0805_1-5]  137.92 95.62 90 bottom
C491  10uF  [CAP0805_1-5]  132.33 90.79 0 top
C492  10uF  [CAP0805_1-5]  124.71 95.62 90 bottom
C493  10uF  [CAP0805_1-5]  132.33 90.79 0 bottom
C494  47uF  [CAP1210_2-75]  141.2 100.31 270 bottom
C495  47uF  [CAP1210_2-75]  141.2 100.31 270 top
C496  2.2uF  [CAP0603_1]  133.99 97.27 180 bottom
C497  2.2uF  [CAP0603_1]  130.05 100.07 270 bottom
C498  2.2uF  [CAP0603_1]  130.3 103.88 90 bottom
C499  47uF  [CAP1210_2-75]  121.41 94.48 90 top
C500  47uF  [CAP1210_2-75]  121.41 94.48 90 bottom
C501  2.2uF  [CAP0603_1]  128.78 100.07 270 bottom
C502  47uF  [CAP1210_2-75]  121.41 100.32 270 bottom
C503  9pF  [CAP0402_0-75]  136.78 86.86 180 bottom
C504  47uF  [CAP1210_2-75]  121.41 100.32 270 top
C505  0.1uF  [CAP0402_0-75]  133.22 93.72 90 bottom
C506  9pF  [CAP0402_0-75]  138.94 86.86 0 bottom
C507  47uF  [CAP1210_2-75]  132.84 87.87 0 top
C508  47uF  [CAP1210_2-75]  132.84 87.87 0 bottom
C509  2.2uF  [CAP0603_1]  135.38 104.13 90 top
C510  2.2uF  [CAP0603_1]  133.73 104.13 90 top
C511  2.2uF  [CAP0603_1]  132.33 104.13 90 top
C512  2.2uF  [CAP0603_1]  130.68 104.13 90 top
C513  2.2uF  [CAP0603_1]  129.29 104.13 90 top
C514  2.2uF  [CAP0603_1]  127.89 104.13 90 top
C516  2.2uF  [CAP0603_1]  79.12 106.54 180 bottom
C517  47uF  [CAP1210_2-75]  79.38 96.51 180 bottom
C518  47uF  [CAP1210_2-75]  79.38 96.51 180 top
C519  10uF  [CAP0805_1-5]  74.68 113.02 0 bottom
C520  10uF  [CAP0805_1-5]  74.68 113.02 0 top
C521  10uF  [CAP0805_1-5]  78.23 113.02 180 top
C522  10uF  [CAP0805_1-5]  78.23 113.02 180 bottom
C523  10uF  [CAP0805_1-5]  69.85 105.4 270 bottom
C524  10uF  [CAP0805_1-5]  69.85 105.4 270 top
C525  10uF  [CAP0805_1-5]  74.68 99.81 0 top
C526  10uF  [CAP0805_1-5]  78.23 99.81 180 top
C527  10uF  [CAP0805_1-5]  78.23 99.81 180 bottom
C528  10uF  [CAP0805_1-5]  74.68 99.81 0 bottom
C529  47uF  [CAP1210_2-75]  73.53 116.32 0 top
C530  47uF  [CAP1210_2-75]  73.53 116.32 0 bottom
C531  2.2uF  [CAP0603_1]  79.12 107.88 180 bottom
C532  2.2uF  [CAP0603_1]  79.88 104.38 180 bottom
C533  2.2uF  [CAP0603_1]  82.8 108.45 0 bottom
C534  47uF  [CAP1210_2-75]  73.53 96.51 0 top
C535  47uF  [CAP1210_2-75]  73.53 96.51 0 bottom
C536  2.2uF  [CAP0603_1]  76.79 102.97 0 bottom
C537  47uF  [CAP1210_2-75]  79.38 116.32 180 bottom
C538  47uF  [CAP1210_2-75]  79.38 116.32 180 top
C539  47uF  [CAP1210_2-75]  66.93 104.89 270 top
C540  47uF  [CAP1210_2-75]  66.93 104.89 270 bottom
C541  2.2uF  [CAP0603_1]  83.19 102.35 0 top
C542  2.2uF  [CAP0603_1]  83.19 104 0 top
C543  2.2uF  [CAP0603_1]  83.19 105.4 0 top
C544  2.2uF  [CAP0603_1]  83.19 107.05 0 top
C545  2.2uF  [CAP0603_1]  83.18 108.37 0 top
C546  2.2uF  [CAP0603_1]  83.18 109.74 0 top
C570  4.7uF  [C603-35X45]  113.92 102.99 90 top
C571  1uF  [CAP0402_0-75]  113.54 99.43 90 top
C1003  0.1uF  [C603-35X45]  169.93 140.2 0 top
C1004  10uF  [C1206-40X70]  169.67 138.29 180 top
C1005  2.2uF  [C805-35X60]  175.77 137.15 90 top
C1006  0.1uF  [C603-35X45]  164.21 135.37 180 top
C1007  0.01uF  [C402-25]  199.14 120 270 top
C1008  0.22uF  [C603-35X45]  196.6 76.19 90 bottom
C1009  10uF  [C1206-40X70]  169.67 135.88 180 top
C1010  10uF  [C1210-70X102]  196.72 119.88 90 top
C1011  10uF  [C1206-40X70]  195.33 125.72 270 top
C1012  10uF  [C1206-40X70]  165.23 130.04 90 top
C1015  0.1uF  [C603-35X45]  194.06 120 270 top
C1016  10uF  [C1206-40X70]  193.04 125.72 270 top
C1017  0.1uF  [C402-25]  169.29 128.51 180 top
C1018  0.1uF  [C402-25]  171.7 128.51 180 top
C1019  2200uF  [CAP300X630UP]  198.37 84.57 0 top
C1020  10uF  [C1206-40X70]  170.69 126.74 180 top
C1021  0.22uF  [C603-35X45]  155.45 21.96 180 top
C1022  0.22uF  [C603-35X45]  155.45 23.74 180 top
C1023  0.22uF  [C603-35X45]  156.08 18.4 90 top
C1024  10uF  [C1206-40X70]  170.69 124.2 180 top
C1025  1uF  [C603-35X45]  183.39 121.53 90 top
C1026  0.1uF  [C402-25RD]  182.88 117.72 180 top
C1027  4.7uF  [C805-35X60]  182.37 119.24 0 top
C1028  1uF  [C805-35X60]  190.25 96.76 180 top
C1029  2.2uF 50V X7R  [C1206-40X70]  169.04 21.07 90 top
C1030  10uF  [C1210-70X102]  164.97 67.17 270 top
C1031  10uF  [C1210-70X102]  168.78 67.17 270 top
C1032  10uF  [C1210-70X102]  182.12 67.17 270 top
C1033  0.1uF  [C402-25]  194.69 97.27 0 top
C1034  120uF  [CAP-FK-D8-65X117]  187.71 65.9 0 top
C1035  10uF  [C1210-70X102]  181.36 98.54 90 top
C1036  10uF  [C1210-70X102]  177.29 98.54 90 top
C1037  0.1uF  [C603-35X45]  188.72 99.43 90 top
C1038  150pF  [C402-25]  198.25 100.07 0 top
C1039  0.015uF  [C402-25]  198.25 101.34 180 top
C1040  1uF  [C603-35X45]  171.32 62.47 90 top
C1041  0.047uF  [C402-25]  196.98 102.61 180 top
C1043  4.7uF  [C805-35X60]  186.82 102.99 90 top
C1044  22uF  [C1210-70X102]  173.61 103.49 270 top
C1045  22uF  [C1210-70X102]  169.93 103.49 270 top
C1046  0.1uF  [C603-35X45]  175.77 60.7 180 top
C1047  0.01uF  [C402-25]  196.98 103.75 180 top
C1049  0.1uF  [C603-35X45]  167.51 59.93 270 top
C1050  0.01uF  [C402-25]  196.98 104.89 180 top
C1051  0.1uF  [C402-25]  193.55 105.78 90 top
C1052  0.01uF  [C402-25]  192.02 105.78 270 top
C1053  220pF  [C402-25]  180.09 57.65 90 top
C1055  220uF  [CAP-VS-F-8383]  181.1 7.48 270 top
C1059  0.047uF  [C402-25RD]  180.85 54.22 180 top
C1060  2200uF  [CAP300X630UP]  186.18 29.58 270 top
C1061  100pF  [C402-25]  178.18 47.74 90 top
C1062  100pF  [C402-25]  169.29 47.49 90 top
C1063  0.1uF  [C603-35X45]  170.69 47.36 270 top
C1064  0.022uF  [C402-25]  173.35 47.36 270 top
C1065  1000pF  [C402-25]  174.62 47.36 270 top
C1069  150pF  [C402-25]  173.1 45.07 90 top
C1070  0.047uF  [C402-25]  174.75 45.07 90 top
C1071  1000pF  [C402-25]  169.67 44.44 0 top
C1136  10uF  [C805-35X60]  25.65 16.12 90 top
C1145  10uF  [C805-35X60]  23.75 21.58 0 top
C1146  10uF  [C805-35X60]  23.75 19.42 0 top
C1161  100pF  [C402-25]  19.81 19.8 270 top
C1182  10uF  [C1206-40X70]  153.42 66.41 270 top
C1183  10uF  [C1206-40X70]  155.83 66.41 270 top
C1187  10uF  [C1210-70X102]  159 63.87 90 top
C1189  1uF  [C603-35X45]  146.94 61.2 180 top
C1190  4.7uF  [C603-35X45]  146.94 59.43 180 top
C1191  NP  [C402-25]  146.94 56 180 top
C1194  47pF  [C402-25]  194.06 115.31 180 bottom
C1197  0.1uF  [C402-25]  161.67 127.37 270 bottom
C1198  1uF  [C402-25]  158.62 127.37 90 bottom
C1199  470pF  [C402-25]  187.71 122.67 270 bottom
C1200  0.1uF  [C603-35X45]  179.83 71.62 0 bottom
C1201  10uF  [C1210-70X102]  189.74 67.17 270 bottom
C1202  10uF  [C1210-70X102]  185.93 67.17 270 bottom
C1204  1000pF  [C402-25]  183.26 105.91 270 bottom
C1205  22uF  [C1210-70X102]  173.74 106.03 270 bottom
C1209  0.1uF  [C402-25]  137.29 148.83 270 top
C1238  0.1uF  [C402-25]  158.37 86.1 270 bottom
C1239  2.2uF  [C603-35X45]  157.73 89.02 90 bottom
C1240  0.22uF  [C603-35X45]  156.08 80.13 180 bottom
C1241  4.7uF  [C603-35X45]  156.08 85.21 180 bottom
C1242  0.22uF  [C603-35X45]  153.67 81.65 270 bottom
C1245  0.1uF  [C402-25]  149.73 95.49 180 bottom
C1249  2.2uF  [C603-35X45]  146.69 81.65 270 bottom
C2023  10uF  [C805-35X60]  45.97 34.91 270 top
C2027  47pF  [C402-25]  40.64 38.34 0 top
C2028  22pF  [C603-35X45]  40 39.61 180 top
C2029  0.1uF  [C603-35X45]  29.84 41.65 0 top
C2030  0.1uF  [C603-35X45]  29.84 43.3 0 top
C2031  22pF  [C603-35X45]  40 45.33 180 top
C2034  47pF  [C402-25]  40.64 46.6 0 top
C2035  4.7nF  [C1206-40X70]  29.34 46.47 180 top
C2037  10uF  [C805-35X60]  43.56 48.76 90 top
C2084  100nF  [C402-25]  55.75 30.22 270 top
C2085  10uF  [C805-35X60]  50.04 30.22 270 top
C2086  10uF  [C805-35X60]  46.23 30.22 90 top
C2087  NP-100nF  [C402-25]  44.32 30.22 90 top
C2115  0.1uF  [C402-25]  36.2 29.71 270 bottom
C2116  4700pF  [C402-25RD]  30.1 33.52 180 bottom
C2117  NP-1uF  [C402-25]  43.69 34.79 270 bottom
C2118  10nF  [C402-25]  45.34 35.42 270 bottom
C2119  1uF  [C402-25]  46.61 35.42 270 bottom
C2120  0.1uF  [C402-25]  36.2 35.04 270 bottom
C2121  0.1uF  [C402-25]  38.73 35.04 90 bottom
C2122  NP-10nF  [C402-25]  45.59 39.23 90 bottom
C2123  NP-100nF  [C402-25]  48.13 39.23 90 bottom
C2124  100nF  [C402-25]  46.74 39.36 90 bottom
C2125  100nF  [C402-25]  44.7 42.53 0 bottom
C2126  10pF  [C402-25]  48.13 47.61 90 bottom
C2127  10pF  [C402-25]  46.99 48 270 bottom
C2128  1uF  [C402-25]  42.93 48.25 90 bottom
C2129  10nF  [C402-25]  44.2 48.25 90 bottom
C3049  0.1uF  [CAP0402_0-75]  119.63 35.06 90 top
C3050  0.1uF  [CAP0402_0-75]  100.86 33.99 0 top
C3051  1uF  [CAP0402_0-5]  114.81 33.44 270 top
C3052  10uF  [CAP0805_1-5]  113.16 33.35 270 top
C3053  10uF  [CAP1206_2]  102.01 31.88 0 top
C3054  0.1uF  [CAP0402_0-75]  116.99 31.78 180 top
C3056  0.01uF  [CAP0402_0-75]  104.14 29.74 90 top
C3057  10uF  [CAP0805_1-5]  115.71 28.54 180 top
C3058  10uF  [CAP0805_1-5]  121.26 27.41 0 top
C3061  0.1uF  [CAP0402_0-75]  115.93 24.93 180 top
C3062  10uF  [CAP0805_1-5]  102.23 24.79 180 top
C3063  0.1uF  [CAP0402_0-75]  120.55 24.61 0 top
C3067  0.01uF  [CAP0402_0-75]  112.73 21.52 180 top
C3068  0.01uF  [CAP0402_0-75]  105.79 19.61 180 top
C3069  0.01uF  [CAP0402_0-75]  109.47 19.61 0 top
C3070  0.01uF  [CAP0402_0-75]  111 19.2 90 top
C3071  1uF  [CAP0402_0-5]  112.12 19.2 90 top
C3096  0.01uF  [CAP0402_0-75]  104.78 29.74 90 bottom
C3097  1uF  [CAP0402_0-5]  103.46 29.74 90 bottom
C3098  0.01uF  [CAP0402_0-75]  113.16 29.49 90 bottom
C3100  0.01uF  [CAP0402_0-75]  111.43 29.03 0 bottom
C3101  0.01uF  [CAP0402_0-75]  102.23 24.79 180 bottom
C3102  1uF  [CAP0402_0-5]  115.87 23.51 90 bottom
C3103  0.01uF  [CAP0402_0-75]  114.73 23.51 90 bottom
C3105  1uF  [CAP0402_0-5]  116.2 19.03 270 bottom
C3106  0.01uF  [CAP0402_0-75]  115.06 19.03 270 bottom
C3107  0.01uF  [CAP0402_0-75]  102.84 18.41 270 bottom
C3108  0.1uF  [CAP0402_0-75]  101.22 17.93 180 bottom
C3109  0.1uF  [CAP0402_0-75]  95.41 17.04 0 bottom
C3110  0.01uF  [CAP0402_0-75]  113.92 16.79 270 bottom
C3111  0.01uF  [CAP0402_0-75]  108.83 16.79 270 bottom
C3114  0.01uF  [CAP0402_0-75]  110.36 16.28 270 bottom
C3116  10uF  [CAP0805_1-5]  127.19 14.86 180 bottom
C3118  0.1uF  [CAP0402_0-75]  127.47 13.21 180 bottom
C3119  0.1uF  [CAP0402_0-75]  107.99 13.74 270 bottom
C3121  0.1uF  [CAP0402_0-75]  109.38 13.73 270 bottom
C3122  0.1uF  [CAP0402_0-75]  98.93 3.45 90 bottom
C3123  22uF  [CAP0805_1-5]  97.03 3.45 270 bottom
C3124  0.1uF  [C402-25RD]  70.36 20.06 0 bottom
C3125  0.047uF  [C402-25RD]  70.36 19.04 0 bottom
C3126  10uF  [C1206-40X70]  79.38 3.04 0 top
C3127  0.1uF  [C402-25RD]  62.99 4.69 0 top
C3128  10uF  [C1206-40X70]  62.74 2.91 0 top
C3129  0.1uF  [C402-25RD]  62.99 6.21 0 top
C3130  10uF  [C1206-40X70]  62.74 8.12 0 top
C3131  0.1uF  [C402-25RD]  66.55 19.42 270 bottom
C3132  0.047uF  [C402-25RD]  65.53 19.42 270 bottom
C3133  0.1uF  [C402-25RD]  46.35 4.56 0 top
C3134  10uF  [C1206-40X70]  46.1 2.78 0 top
C3135  0.1uF  [C402-25RD]  46.35 6.09 0 top
C3136  10uF  [C1206-40X70]  46.1 7.99 0 top
C3137  0.1uF  [C402-25RD]  63.5 19.42 270 bottom
C3138  0.047uF  [C402-25RD]  62.48 19.42 270 bottom
C3139  0.1uF  [C402-25RD]  29.72 4.56 0 top
C3140  10uF  [C1206-40X70]  29.46 2.78 0 top
C3141  0.1uF  [C402-25RD]  29.72 6.09 0 top
C3142  10uF  [C1206-40X70]  29.46 7.99 0 top
C3143  0.1uF  [C402-25RD]  58.55 19.04 180 bottom
C3144  0.047uF  [C402-25RD]  58.55 20.06 180 bottom
C3145  0.1uF  [C402-25]  58.29 47.74 270 top
C3146  0.1uF  [CAP0402_0-75]  132.72 103.37 90 bottom
C3147  0.1uF  [CAP0402_0-75]  81.28 103.11 180 bottom
C3148  2.2uF  [CAP0603_1]  131.32 100.07 270 bottom
C3149  2.2uF  [CAP0603_1]  83.19 107.05 0 bottom
D1  BZX84C6V8LT1G  [SOT23-123_1-2]  152.25 130.8 180 bottom
D2  SZMM3Z10VST1G  [DIO_SOD323_1-1]  161.24 96.48 180 top
D1002  PDS5100H-13-01  [DIODE-POWERDI5]  194.94 69.08 90 bottom
D1003  MMSZ5237BS-7-F  [SOD323]  176.02 65.01 0 top
D1004  PMEG6010CEJ,115  [SOD323]  185.8 100.19 180 top
D1005  BAS516,115  [SOD523]  173.86 62.6 0 top
D1006  CUS05S40,H3F  [SOD323]  178.44 62.6 0 top
D1007  BAS516,115  [SOD523]  168.78 62.47 180 top
D1008  BAT54HT1G  [SOD323]  164.34 49.77 270 top
D1018  SMCJ14A-13-F  [SMC-80X128]  151.51 27.93 270 bottom
D1019  SMCJ30A-13-F  [SMC-80X128]  151.51 18.4 90 bottom
D1020  B170-13-F  [SMA2-78SQ]  186.18 107.56 90 bottom
D3019  TPD1E05U06DPY  [DIO_DFN0402_0-5]  131.7 18.44 180 top
D3020  TPD1E05U06DPY  [DIO_DFN0402_0-5]  133.73 18.44 0 top
D3021  TPD1E05U06DPY  [DIO_DFN0402_0-5]  137.65 18.44 180 top
D3022  TPD1E05U06DPY  [DIO_DFN0402_0-5]  139.68 18.44 0 top
D3029  TPD1E05U06DPY  [DIO_DFN0402_0-5]  128.65 16.79 180 top
D3030  TPD1E05U06DPY  [DIO_DFN0402_0-5]  130.68 16.79 0 top
D3031  TPD1E05U06DPY  [DIO_DFN0402_0-5]  134.73 16.79 180 top
D3032  TPD1E05U06DPY  [DIO_DFN0402_0-5]  136.76 16.79 0 top
D3033  TPD1E05U06DPY  [DIO_DFN0402_0-5]  140.57 16.79 180 top
D3034  TPD1E05U06DPY  [DIO_DFN0402_0-5]  142.6 16.79 0 top
D3036  SMCJ15CA  [DIO_SMC]  97.54 10.19 90 bottom
DS1000  LED_GRN  [LED1206-59X59]  149.86 10.4 0 top
FL1  120E  [EMIFIL_BLM18P_0603_0-8]  100.46 104.38 180 top
FL3  120E  [EMIFIL_BLM18P_0603_0-8]  91.82 97.27 180 bottom
FL4  120E  [EMIFIL_BLM18P_0603_0-8]  107.57 104.38 180 top
FL5  120E  [EMIFIL_BLM18P_0603_0-8]  104.39 94.22 0 top
FL6  120E  [EMIFIL_BLM18P_0603_0-8]  113.66 96.26 180 top
FL9  120E  [EMIFIL_BLM18P_0603_0-8]  88.95 42.71 0 top
FL11  120E  [EMIFIL_BLM18P_0603_0-8]  92.96 42.53 0 top
FL12  120E  [EMIFIL_BLM18P_0603_0-8]  97.18 42.53 0 top
FL13  120E  [EMIFIL_BLM18P_0603_0-8]  108.66 42.59 0 top
FL14  120E  [EMIFIL_BLM18P_0603_0-8]  102.23 42.53 0 top
FL15  120E  [EMIFIL_BLM18P_0603_0-8]  123.19 44.06 0 top
FL16  120E  [EMIFIL_BLM18P_0603_0-8]  91.69 103.75 180 bottom
FL18  120E  [EMIFIL_BLM18P_0603_0-8]  104.39 94.35 0 bottom
FL19  120E  [EMIFIL_BLM18P_0603_0-8]  107.57 104.38 180 bottom
FL20  120E  [EMIFIL_BLM18P_0603_0-8]  91.82 97.14 180 top
FL21  120E  [EMIFIL_BLM18P_0603_0-8]  72.52 79.11 270 bottom
FL26  120E  [EMIFIL_BLM18P_0603_0-8]  108.58 42.53 0 bottom
FL27  120E  [EMIFIL_BLM18P_0603_0-8]  97.16 42.53 0 bottom
FL28  120E  [EMIFIL_BLM18P_0603_0-8]  102.23 42.53 0 bottom
FL29  120E  [EMIFIL_BLM18P_0603_0-8]  116.2 101.46 90 top
FL1000  DLW21SN121HQ2  [EMI-36X15-DLW21]  160.4 136.51 90 top
FL1001  DLW21SN121HQ2  [EMI-36X15-DLW21]  173.61 137.4 90 top
FL1002  DLW21SN900HQ2  [EMI-36X15-DLW21-RDPADS]  179.45 135.75 90 bottom
FL1003  DLW21SN900HQ2  [EMI-36X15-DLW21-RDPADS]  181.48 135.75 90 bottom
FL3011  120E  [EMIFIL_BLM18A_0603]  117.22 34.06 180 top
FL3012  120E  [EMIFIL_BLM18A_0603]  118.52 29.02 270 top
FL3013  120E  [EMIFIL_BLM18A_0603]  118.54 25.7 90 top
FL3014  120E  [EMIFIL_BLM18A_0603]  118.64 23.09 180 top
FL3015  DLW21SN900HQ2  [EMI-36X15-DLW21-RDPADS]  129.67 22.61 270 top
FL3019  DLW21SN900HQ2  [EMI-36X15-DLW21-RDPADS]  132.72 20.98 270 top
FL3020  DLW21SN900HQ2  [EMI-36X15-DLW21-RDPADS]  138.66 20.98 270 top
FL3023  DLW21SN900HQ2  [EMI-36X15-DLW21-RDPADS]  135.74 19.33 270 top
FL3024  DLW21SN900HQ2  [EMI-36X15-DLW21-RDPADS]  141.58 19.33 270 top
FL3026  0.47uF  [EMIFIL_NFM21P_0805]  98.42 17.04 0 bottom
FL3028  DLW21SN900HQ2  [EMI-36X15-DLW21-RDPADS]  154.81 135.75 90 bottom
FL3029  DLW21SN900HQ2  [EMI-36X15-DLW21-RDPADS]  156.84 135.75 90 bottom
FL3030  DLW21SN900HQ2  [EMI-36X15-DLW21-RDPADS]  108.71 10.91 270 bottom
FL*  -  [unnamed#3]  116.88 19.99 270 top
J1000  1932258-1-USB3  [CON-1932258]  180.34 143.5 180 top
J1001  1932258-1-USB3  [CON-1932258]  155.7 143.5 180 top
J1003  Phoenix Contacts - 1757268  [CONN4-MSTBA]  156.59 9.13 180 top
J1010  NP  [JUMP1X2-6040]  196.85 113.53 0 top
J1011  MIPI-QSH-030  [QSH-030-01-F]  49.4 62.35 90 top
J3003  CON_MUSB_20_F  [CON_USB20_472720001_S_R_T_7]  133.72 6.22 0 top
J3005  CON_JACK4_D4S20G-400A5  [CON_JACK4_D4S20G-400A5_P_R_T_10-6]  106.17 7.86 0 top
JZ2000  Molex 34826-0124  [MOLEX-34826-0124]  11.05 36.44 270 top
L1  1uH  [IND1008_1-2]  137.92 91.81 270 top
L2  1uH  [IND1008_1-2]  137.92 102.99 90 top
L3  0.47uH  [IND1008_1-2]  124.71 91.81 270 top
L4  0.47uH  [IND1008_1-2]  124.71 102.99 90 top
L5  1uH  [IND1008_1-2]  128.78 89.91 270 top
L6  0.47uH  [IND1008_1-2]  70.87 113.02 180 top
L7  0.47uH  [IND1008_1-2]  82.04 113.02 0 top
L8  0.47uH  [IND1008_1-2]  70.87 99.81 180 top
L9  0.47uH  [IND1008_1-2]  82.04 99.81 0 top
L10  1uH  [IND1008_1-2]  68.96 108.96 180 top
L27  10uH  [IND2-LQH3N]  80.64 11.8 180 bottom
L40  100uH  [IND-MSS7341]  80.77 5.58 270 bottom
L51  MPZ1608S102ATA00  [L603-35X45]  77.85 5.58 90 top
L60  BLM18HE152SN1  [L603-35X45]  87.88 11.17 180 bottom
L61  BLM18HE152SN1  [L603-35X45]  86.23 12.82 180 bottom
L62  BLM18HE152SN1  [L603-35X45]  83.82 12.05 270 bottom
L1000  3.3uH, 5A  [IND2-7030D]  191.52 78.35 90 bottom
L1001  5.6uH - IHLP5050FDER5R6M01  [IND-IHLP5050]  177.04 83.05 0 top
L1002  IHLP2020CZER2R2M01  [IND-IHLP2020]  188.09 125.59 0 top
L1003  300uH  [IND2-ATCA-06]  161.8 33.39 90 top
L1004  3.3uH, 9A  [IND-DFEG10040]  177.42 18.28 0 top
L1005  2.2uH  [IND-IHLP-COMBO]  181.48 108.83 90 top
L1023  DFE252012PD-2R2M  [IND2520-40X80]  24.38 12.44 180 top
L1040  XAL4020-222MEB  [COIL-XAL40]  149.48 66.41 90 top
L2004  220Ohm  [L603-35X45]  43.69 34.79 270 top
L2005  120nH  [L603-35X45]  40 41.52 180 top
L2006  AE2002  [CHOKE4-AE2002]  34.92 42.41 0 top
L2007  120nH  [L603-35X45]  40 43.42 180 top
L2008  220Ohm  [L603-35X45]  40 48.38 0 top
L2017  NP-220Ohm  [L603-35X45]  48.13 30.22 270 top
L2018  MPZ1608S102ATA00  [L603-35X45]  61.21 5.45 90 top
L2019  BLM18HE152SN1  [L603-35X45]  71.25 11.04 180 bottom
L2020  BLM18HE152SN1  [L603-35X45]  69.6 12.69 180 bottom
L2021  BLM18HE152SN1  [L603-35X45]  67.18 11.93 270 bottom
L2022  10uH  [IND2-LQH3N]  64.01 11.67 180 bottom
L2023  100uH  [IND-MSS7341]  64.13 5.45 270 bottom
L2024  MPZ1608S102ATA00  [L603-35X45]  44.58 5.32 90 top
L2025  BLM18HE152SN1  [L603-35X45]  54.61 10.91 180 bottom
L2026  BLM18HE152SN1  [L603-35X45]  52.96 12.56 180 bottom
L2027  BLM18HE152SN1  [L603-35X45]  50.55 11.8 270 bottom
L2028  10uH  [IND2-LQH3N]  47.37 11.55 180 bottom
L2029  100uH  [IND-MSS7341]  47.5 5.32 270 bottom
L2030  MPZ1608S102ATA00  [L603-35X45]  27.94 5.32 90 top
L2031  BLM18HE152SN1  [L603-35X45]  37.97 10.91 180 bottom
L2032  BLM18HE152SN1  [L603-35X45]  36.32 12.56 180 bottom
L2033  BLM18HE152SN1  [L603-35X45]  33.91 11.8 270 bottom
L2034  10uH  [IND2-LQH3N]  30.73 11.55 180 bottom
L2035  100uH  [IND-MSS7341]  30.86 5.32 270 bottom
M1000  -  [MHP93-200]  134.11 134.86 0 top
M1001  -  [MHP93-200]  127.63 145.15 0 top
NOREF  -  []  -528.41 -134.96 0 top
NOREF#2  -  []  -190.29 -38.49 0 top
NOREF#3  -  []  61.67 -42.96 0 top
NOREF#4  -  [unnamed#2]  5.08 5.83 0 top
NOREF#5  -  [unnamed#2]  5.46 146.8 0 top
NOREF#6  -  []  -151.03 -50.71 0 top
NOREF#7  -  []  -524.79 -99.22 0 top
NOREF#8  -  []  -136.47 60.01 0 top
NOREF#9  -  [unnamed#2]  198.63 6.34 0 top
NOREF#10  -  [unnamed#2]  196.6 146.8 0 top
NOREF#11  -  []  535.37 81.61 0 top
P5  FAKRA  [CONN-ST-FAKRA]  88.65 5.96 180 top
P6  FAKRA  [CONN-ST-FAKRA]  72.01 5.83 180 top
P7  FAKRA  [CONN-ST-FAKRA]  55.37 5.7 180 top
P8  FAKRA  [CONN-ST-FAKRA]  38.73 5.7 180 top
Q13  BSS138  [SOT23-28X44-GSD]  56.39 59.17 270 top
Q1001  BSS138PS  [SOT363-16X45]  165.23 124.7 0 top
Q1002  SQJ422EP  [PWR-Q5A-SLPS319]  160.15 17.13 0 top
Q1003  BSZ068N06NSATMA1  [TSDSON8]  173.23 73.52 0 top
Q1004  BSZ068N06NSATMA1  [TSDSON8]  177.67 73.52 0 top
Q1005  BSZ068N06NSATMA1  [TSDSON8]  168.78 72.89 180 top
Q1006  BSZ068N06NSATMA1  [TSDSON8]  182.12 72.89 180 top
Q1007  BSZ068N06NSATMA1  [TSDSON8]  184.53 98.67 0 bottom
Q1008  BSZ068N06NSATMA1  [TSDSON8]  180.85 102.86 90 bottom
R1  10K_1%  [RES0402_0-5]  148.21 134.31 0 top
R4  9.09K_1%  [RES0402_0-5]  148.21 133.06 180 top
R20  2.2K  [RES0201_0-5]  114.17 116.32 270 top
R23  2.2K  [RES0201_0-5]  142.88 81.9 270 top
R25  2.2K  [RES0201_0-5]  112.9 116.32 270 top
R27  10K_1%  [RES0201_0-5]  148.46 75.68 270 top
R37  2.2K  [RES0201_0-5]  104.65 26.28 180 top
R38  2.2K  [RES0201_0-5]  104.65 27.29 180 top
R43  10K_1%  [RES0201_0-5]  55.12 90.29 0 top
R46  10K_1%  [RES0402_0-5]  160.59 109.64 180 top
R54  2.2K  [RES0201_0-5]  156.08 75.68 270 top
R56  0E  [RES0402_0-5]  152.78 71.24 0 top
R66  10K_1%  [RES0201_0-5]  154.81 75.68 270 top
R67  0E  [RES0402_0-5]  78.74 73.65 90 top
R74  2.2K  [RES0201_0-5]  70.1 58.54 0 top
R77  0E  [RES0402_0-5]  71.88 70.98 90 top
R79  2.2K  [RES0201_0-5]  41.91 71.87 0 top
R80  10K_1%  [RES0201_0-5]  152.78 72.51 0 top
R81  2.2K  [RES0201_0-5]  41.91 74.41 0 top
R84  11K_1%  [RES0402_0-5]  80.01 66.66 0 top
R86  10K_1%  [RES0402_0-5]  57.02 70.09 0 top
R87  3K_1%  [RES0402_0-5]  80.01 67.99 180 top
R88  0E  [RES0402_0-5]  75.57 67.55 0 top
R89  0E  [RES0402_0-5]  72.39 67.45 180 top
R93  0E  [RES0402_0-5]  81.76 64.4 180 top
R105  2.2K  [RES0201_0-5]  70.1 57.27 0 top
R106  2.2K  [RES0201_0-5]  70.1 60.44 0 top
R108  0E  [RES0402_0-5]  70.48 49.65 270 top
R109  0E  [RES0402_0-5]  71.63 49.65 270 top
R113  10K_1%  [RES0201_0-5]  38.61 58.66 180 top
R114  10K_1%  [RES0201_0-5]  70.23 48.12 180 top
R115  10K_1%  [RES0201_0-5]  71.88 48.12 0 top
R120  0E  [RES0402_0-5]  84.58 54.85 270 top
R121  2.2K  [RES0201_0-5]  70.13 56.05 0 top
R124  10K_1%  [RES0201_0-5]  38.86 52.82 180 top
R132  4.02K  [R402-25]  80.64 14.09 180 bottom
R137  0E  [RES0402_0-5]  69.09 49.65 270 top
R138  22E_1%  [RES0402_0-5]  67.82 49.65 90 top
R144  10K_1%  [RES0402_0-5]  84.71 46.85 90 top
R149  10K_1%  [RES0402_0-5]  82.8 45.2 180 top
R150  10K_1%  [RES0402_0-5]  82.8 44.06 180 top
R151  10K_1%  [RES0402_0-5]  82.8 42.92 180 top
R152  22E_1%  [RES0402_0-5]  82.68 47.87 0 top
R153  10K_1%  [RES0201_0-5]  81.69 46.14 0 top
R154  10K_1%  [RES0402_0-5]  80.95 42.26 90 top
R156  10K_1%  [RES0402_0-5]  79.88 42.26 90 top
R158  10K_1%  [RES0402_0-5]  77.62 43.02 90 top
R161  10K_1%  [RES0402_0-5]  76.45 45.96 0 top
R162  10K_1%  [RES0402_0-5]  76.45 44.59 0 top
R164  0E  [RES0402_0-5]  75.97 47.74 0 top
R168  22E_1%  [RES0402_0-5]  116.46 95.62 270 top
R169  10K_1%  [RES0402_0-5]  148.49 132.98 180 bottom
R170  16.5K_1%  [RES0402_0-5]  148.51 131.79 180 bottom
R171  3.4K_1%  [RES0402_0-5]  148.51 130.77 0 bottom
R180  10K_1%  [RES0402_0-5]  120.26 87.68 180 bottom
R201  49.9E_1%  [RES0402_0-5]  102.24 80.57 90 bottom
R202  49.9E_1%  [RES0402_0-5]  99.06 80.58 90 bottom
R203  49.9E_1%  [RES0402_0-5]  97.03 80.18 0 bottom
R204  10K_1%  [RES0201_0-5]  110.95 80.15 90 bottom
R205  3.01K_1%  [RES0201_0-5]  105.03 80.13 0 bottom
R206  3.01K_1%  [RES0201_0-5]  101.09 80.13 0 bottom
R207  3.01K_1%  [RES0201_0-5]  95.45 80.13 180 bottom
R208  49.9E_1%  [RES0402_0-5]  98.25 79.77 90 bottom
R209  100E_1%  [RES0201_0-5]  109.45 79.77 90 bottom
R210  500E_0.1%  [RES0402_1]  103.45 79.75 135 bottom
R213  49.9E_1%  [RES0402_0-5]  97.03 79.3 180 bottom
R214  49.9E_1%  [RES0402_0-5]  101.85 79.34 0 bottom
R215  100E_1%  [RES0201_0-5]  108.66 78.98 90 bottom
R216  3.01K_1%  [RES0201_0-5]  100.05 78.93 270 bottom
R217  100E_1%  [RES0201_0-5]  110.26 78.96 270 bottom
R218  500E_0.1%  [RES0402_1]  111.59 78.96 90 bottom
R225  10K_1%  [RES0201_0-5]  106.27 72.43 90 bottom
R227  10K_1%  [RES0402_0-5]  136.09 71.24 90 bottom
R228  10K_1%  [RES0402_0-5]  118.67 69.89 90 bottom
R230  10K_1%  [RES0402_0-5]  136.09 69.33 90 bottom
R232  10K_1%  [RES0402_0-5]  118.67 67.99 90 bottom
R233  240E_1%  [RES0201_0-5]  109.86 65.34 315 bottom
R234  500E_0.1%  [RES0402_1]  99.06 64.38 90 bottom
R235  10K_1%  [RES0402_0-5]  137.26 64.18 90 bottom
R236  3.01K_1%  [RES0201_0-5]  104.27 64.12 0 bottom
R237  500E_0.1%  [RES0402_1]  101.47 63.74 270 bottom
R238  500E_0.1%  [RES0402_1]  99.06 62.46 270 bottom
R239  10K_1%  [RES0402_0-5]  137.26 62.27 90 bottom
R240  22E_1%  [RES0402_0-5]  80.39 62.22 180 bottom
R242  240E_1%  [RES0201_0-5]  127.89 58.92 90 bottom
R243  240E_1%  [RES0201_0-5]  126.75 58.92 90 bottom
R247  22E_1%  [RES0402_0-5]  93.48 55.35 180 bottom
R253  100K  [RES0402_0-5]  83.29 47.39 90 bottom
R264  22E_1%  [RES0402_0-5]  93.49 56.79 180 bottom
R272  10K_1%  [RES0402_0-5]  133.1 113.4 0 bottom
R273  10K_1%  [RES0402_0-5]  127.25 102.22 270 bottom
R276  DNI  [RES0402_0-5]  135.64 95.24 90 bottom
R277  0E  [RES0402_0-5]  134.62 95.24 90 bottom
R280  10K_1%  [RES0402_0-5]  89.03 116.7 270 top
R281  DNI  [RES0402_0-5]  85.09 68.82 180 bottom
R287  0E  [RES0402_0-5]  55.75 108.19 0 top
R288  0E  [RES0402_0-5]  55.81 105.66 0 top
R471  0E  [RES0402_0-5]  157.28 98.01 0 top
R472  240E  [RES0402_0-5]  165.99 97.02 270 top
R473  240E  [RES0402_0-5]  164.34 96.64 180 top
R493  10K_1%  [RES0402_0-5]  132.46 106.29 270 top
R494  0E  [RES0402_0-5]  78.61 123.94 270 top
R495  0E  [RES0402_0-5]  55.63 102.99 0 top
R496  0E  [RES0402_0-5]  77.34 123.94 270 top
R502  0E  [RES0402_0-5]  135 85.08 90 top
R503  0E  [RES0402_0-5]  55.63 100.57 180 top
R504  0E  [RES0402_0-5]  132.08 85.21 0 top
R515  10K_1%  [RES0402_0-5]  63.3 105.48 270 bottom
R522  0E  [RES0402_0-5]  127.25 98.41 90 bottom
R625  10K  [R201-6P6SPC]  57.66 61.84 270 top
R1000  4.99K  [R402-25]  177.29 136.77 270 top
R1001  100K  [R402-25]  169.29 134.23 180 top
R1002  100K  [R402-25]  169.29 133.09 180 top
R1003  80.6K  [R402-25]  169.29 131.94 180 top
R1004  19.1K  [R402-25]  169.29 130.8 180 top
R1005  2K  [R402-25]  169.29 129.66 180 top
R1006  100K  [R402-25]  175.9 129.15 90 top
R1007  0  [R402-25]  176.91 129.15 90 top
R1008  0  [R402-25]  177.93 129.15 90 top
R1009  10K  [R402-25]  167.26 124.7 90 top
R1010  0  [R402-25]  175.9 126.61 90 top
R1011  10K  [R402-25]  176.91 126.61 270 top
R1012  0.010  [R0612]  158.12 14.34 0 top
R1013  0  [R402-25]  183.39 124.07 90 top
R1014  3.01  [R402-25]  164.97 74.41 180 top
R1015  0  [R402-25]  186.44 74.41 180 top
R1016  10K  [R402-25]  182.88 116.7 180 top
R1017  6.04k  [R402-25]  194.69 93.84 0 top
R1018  2K  [R402-25]  194.69 94.99 180 top
R1019  0.008-PRL1632-R008-F-T1  [R0612]  174.37 68.82 180 top
R1020  0  [R402-25]  177.67 68.44 270 top
R1021  3.01  [R402-25]  178.94 68.44 90 top
R1022  0  [R402-25]  193.68 96.13 180 top
R1023  200  [R402-25]  199.14 97.65 0 top
R1024  34.8K  [R402-25]  196.98 97.65 0 top
R1025  20K  [R402-25]  196.98 98.8 180 top
R1026  3.01K  [R402-25]  196.34 100.7 270 top
R1027  0  [R402-25]  191.01 105.78 90 top
R1028  NP  [R402-25]  189.99 105.78 90 top
R1029  0  [R402-25]  188.98 105.78 270 top
R1030  100  [R402-25]  181.99 58.28 0 top
R1031  100  [R402-25]  181.99 57.01 0 top
R1032  10K  [R402-25]  195.58 107.94 270 top
R1033  10K  [R402-25]  180.85 55.49 180 top
R1034  10  [R402-25]  166.88 50.41 0 top
R1035  100K  [R402-25]  180.34 49.52 0 top
R1036  3.16K  [R603-35X45]  173.99 49.27 0 top
R1037  10  [R402-25]  166.88 49.14 0 top
R1038  1.82K  [R603-35X45]  182.5 48.88 270 top
R1039  10  [R402-25]  180.34 48.25 180 top
R1040  NP  [R402-25]  168.02 47.49 90 top
R1041  5.36K  [R603-35X45]  176.4 47.49 90 top
R1042  110K  [R402-25]  172.21 47.36 270 top
R1045  93.1K  [R402-25]  169.67 45.46 0 top
R1046  0  [R402-25]  171.96 45.07 90 top
R1071  475K  [R402-25]  21.08 19.8 90 top
R1072  150K  [R402-25]  21.08 17.26 90 top
R1074  475K  [R402-25]  20.57 13.07 270 top
R1091  0  [R402-25]  146.94 62.6 0 top
R1106  51  [R402-25]  145.29 57.77 90 top
R1107  95.3K  [R402-25]  146.94 57.27 180 top
R1108  10K  [R402-25]  149.61 56 0 top
R1109  3.32K  [R402-25]  154.31 56 180 top
R1110  10K  [R402-25]  156.84 55.62 90 top
